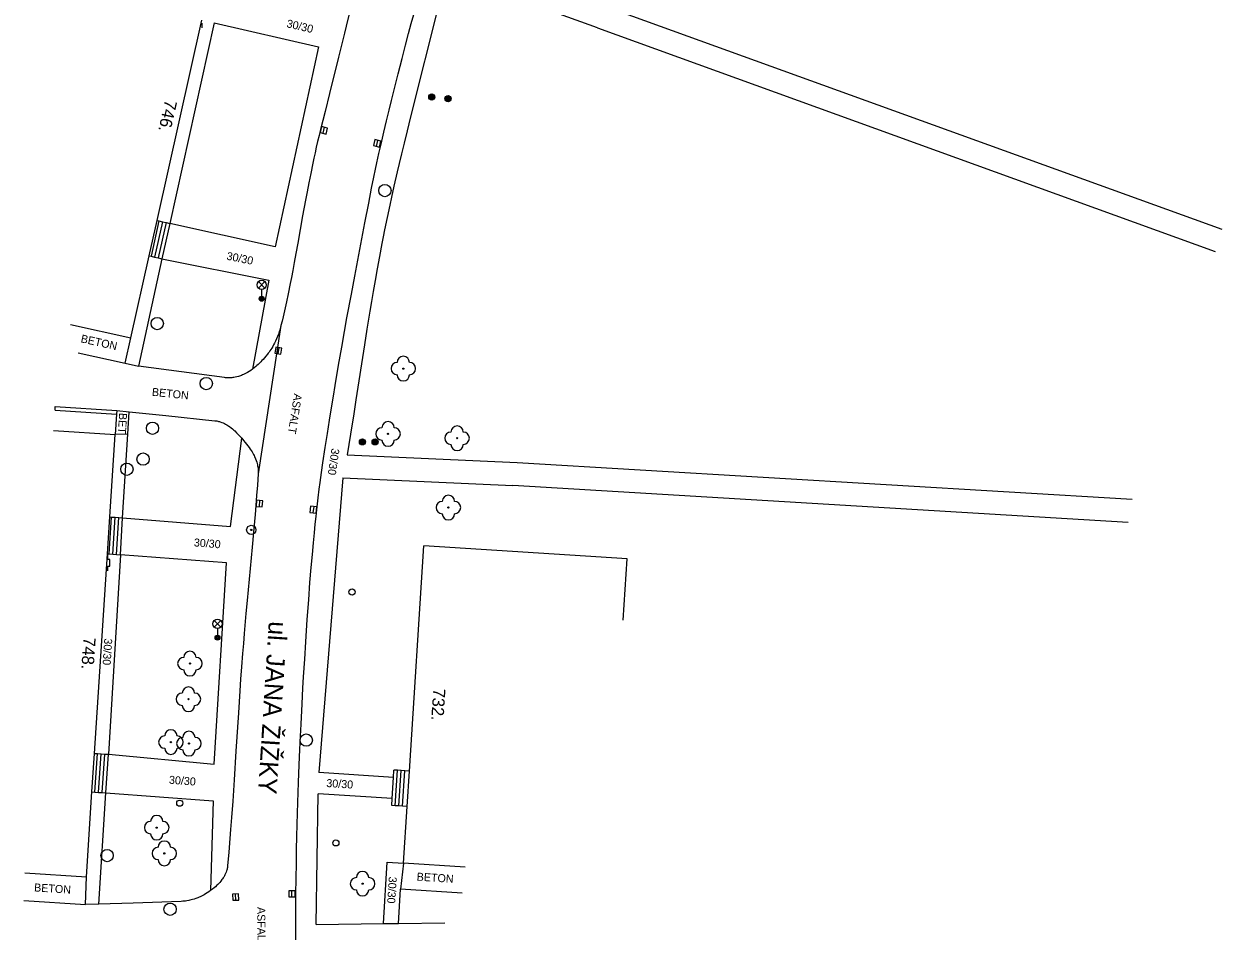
# Model space of a CAD drawing. Extents: x -539515 to -538098, y -1182060 to -1180157.
# Drawn here: x -538326.4 to -538229.1, y -1181130.7 to -1181057.1 of the extents above; entities that cross this region are included whole.
import ezdxf

# ---------------------------------------------------------------- set-up
doc = ezdxf.new("R2010")
doc.units = 0
for name, color, linetype in [('Vrstva 1', 7, 'Continuous'), ('Vrstva 13', 7, 'Continuous'), ('Vrstva 21', 7, 'Continuous'), ('Vrstva 22', 7, 'Continuous'), ('Vrstva 24', 7, 'Continuous'), ('Vrstva 25', 7, 'Continuous'), ('Vrstva 27', 7, 'Continuous'), ('Vrstva 28', 7, 'Continuous'), ('Vrstva 33', 7, 'Continuous'), ('Vrstva 40', 7, 'Continuous'), ('Vrstva 47', 7, 'Continuous'), ('Vrstva 49', 7, 'Continuous'), ('Vrstva 68', 7, 'Continuous'), ('Vrstva 88', 7, 'Continuous')]:
    doc.layers.add(name, color=color, linetype=linetype)

msp = doc.modelspace()

# ---------------------------------------------------------------- linework, layer by layer
at = {"layer": 'Vrstva 1'}
for p, q in [((-538322.649, -1181081.468), (-538317.77, -1181082.56)), ((-538324.03, -1181090.076), (-538319.04, -1181090.4)), ((-538277.453, -1181100.501), (-538293.97, -1181099.45)), ((-538277.771, -1181105.491), (-538277.453, -1181100.501)), ((-538326.36, -1181126.006), (-538321.37, -1181126.33)), ((-538290.62, -1181125.538), (-538295.61, -1181125.22))]:
    msp.add_line(p, q, dxfattribs=at)
for points in [[(-538315.634, -1181073.02), (-538311.991, -1181056.744)], [(-538316.276, -1181075.888), (-538315.634, -1181073.02)], [(-538317.77, -1181082.56), (-538316.276, -1181075.888)], [(-538319.474, -1181097.092), (-538319.04, -1181090.4)], [(-538319.668, -1181100.091), (-538319.474, -1181097.092)], [(-538295.133, -1181117.731), (-538293.97, -1181099.45)], [(-538320.719, -1181116.296), (-538319.668, -1181100.091)], [(-538320.923, -1181119.43), (-538320.719, -1181116.296)], [(-538295.317, -1181120.61), (-538295.133, -1181117.731)], [(-538321.37, -1181126.33), (-538320.923, -1181119.43)], [(-538295.61, -1181125.22), (-538295.317, -1181120.61)]]:
    msp.add_lwpolyline(points, dxfattribs=at)
at = {"layer": 'Vrstva 13'}
for p, q in [((-538279.867, -1181057.368), (-538292.13, -1181052.94)), ((-538292.748, -1181055.46), (-538295.047, -1181064.595)), ((-538229.137, -1181073.742), (-538279.247, -1181055.628)), ((-538310.98, -1181056.97), (-538314.599, -1181073.251)), ((-538310.98, -1181056.97), (-538302.53, -1181058.92)), ((-538279.867, -1181057.368), (-538229.687, -1181075.542)), ((-538302.53, -1181058.92), (-538306.03, -1181075.17)), ((-538315.477, -1181073.054), (-538316.118, -1181075.923)), ((-538315.184, -1181073.12), (-538315.825, -1181075.989)), ((-538314.891, -1181073.185), (-538315.532, -1181076.054)), ((-538314.599, -1181073.251), (-538315.24, -1181076.12)), ((-538306.03, -1181075.17), (-538314.599, -1181073.251)), ((-538315.24, -1181076.12), (-538317.15, -1181084.85)), ((-538315.24, -1181076.12), (-538306.55, -1181077.86)), ((-538306.55, -1181077.86), (-538307.89, -1181085.09)), ((-538305.57, -1181081.55), (-538307.42, -1181093.59)), ((-538318.229, -1181084.609), (-538317.77, -1181082.56)), ((-538322.029, -1181083.758), (-538318.229, -1181084.609)), ((-538318.229, -1181084.609), (-538317.15, -1181084.85)), ((-538318.929, -1181088.759), (-538319.04, -1181090.4)), ((-538318, -1181090.37), (-538319.04, -1181090.4)), ((-538309.67, -1181097.87), (-538308.75, -1181090.71)), ((-538300.2, -1181092.06), (-538286.395, -1181092.686)), ((-538286.395, -1181092.686), (-538236.432, -1181095.639)), ((-538300.55, -1181093.92), (-538302.49, -1181117.86)), ((-538300.55, -1181093.92), (-538286.745, -1181094.546)), ((-538236.752, -1181097.559), (-538286.745, -1181094.546)), ((-538319.522, -1181100.099), (-538319.328, -1181097.101)), ((-538319.222, -1181100.119), (-538319.028, -1181097.121)), ((-538318.923, -1181100.138), (-538318.729, -1181097.14)), ((-538318.6, -1181100.16), (-538318.43, -1181097.16)), ((-538318.43, -1181097.16), (-538309.67, -1181097.87)), ((-538318.6, -1181100.16), (-538319.58, -1181116.37)), ((-538309.99, -1181100.83), (-538318.6, -1181100.16)), ((-538310.99, -1181117.18), (-538309.99, -1181100.83)), ((-538320.68, -1181119.445), (-538320.478, -1181116.312)), ((-538320.38, -1181119.464), (-538320.178, -1181116.331)), ((-538320.081, -1181119.483), (-538319.879, -1181116.35)), ((-538319.782, -1181119.503), (-538319.58, -1181116.37)), ((-538319.58, -1181116.37), (-538310.99, -1181117.18)), ((-538296.438, -1181118.247), (-538302.49, -1181117.86)), ((-538296.284, -1181120.548), (-538296.1, -1181117.669)), ((-538295.985, -1181120.567), (-538295.801, -1181117.688)), ((-538295.685, -1181120.586), (-538295.501, -1181117.707)), ((-538320.368, -1181128.544), (-538319.782, -1181119.503)), ((-538319.782, -1181119.503), (-538311.08, -1181120.14)), ((-538311.08, -1181120.14), (-538311.29, -1181127.44)), ((-538302.71, -1181130.19), (-538302.55, -1181119.58)), ((-538296.548, -1181119.964), (-538302.55, -1181119.58)), ((-538297.25, -1181130.12), (-538296.933, -1181125.136)), ((-538296.933, -1181125.136), (-538295.61, -1181125.22)), ((-538295.61, -1181125.22), (-538295.85, -1181127.33)), ((-538321.45, -1181128.58), (-538321.37, -1181126.33)), ((-538296.026, -1181130.104), (-538295.85, -1181127.33)), ((-538290.86, -1181127.648), (-538295.85, -1181127.33)), ((-538326.44, -1181128.256), (-538321.45, -1181128.58))]:
    msp.add_line(p, q, dxfattribs=at)
for points in [[(-538295.047, -1181064.595), (-538295.329, -1181065.738), (-538295.572, -1181066.739), (-538295.782, -1181067.615), (-538295.963, -1181068.383), (-538296.12, -1181069.054), (-538296.389, -1181070.231), (-538296.586, -1181071.114), (-538296.731, -1181071.777), (-538296.944, -1181072.773), (-538297.15, -1181073.77), (-538297.264, -1181074.338)], [(-538315.634, -1181073.02), (-538315.477, -1181073.054), (-538315.184, -1181073.12), (-538314.891, -1181073.185), (-538314.599, -1181073.251)], [(-538297.264, -1181074.338), (-538297.373, -1181074.888), (-538297.577, -1181075.956), (-538297.761, -1181076.958), (-538297.929, -1181077.899), (-538298.082, -1181078.782), (-538298.223, -1181079.61), (-538298.352, -1181080.387), (-538298.589, -1181081.845), (-538298.791, -1181083.122)], [(-538316.276, -1181075.888), (-538316.118, -1181075.923), (-538315.825, -1181075.989), (-538315.532, -1181076.054), (-538315.24, -1181076.12)], [(-538298.791, -1181083.122), (-538299.485, -1181087.593), (-538299.66, -1181088.711), (-538299.926, -1181090.386), (-538300.062, -1181091.223), (-538300.2, -1181092.06)], [(-538318, -1181090.37), (-538317.886, -1181088.565)], [(-538318.43, -1181097.16), (-538318, -1181090.37)], [(-538319.474, -1181097.092), (-538319.328, -1181097.101), (-538319.028, -1181097.121), (-538318.729, -1181097.14), (-538318.43, -1181097.16)], [(-538319.668, -1181100.091), (-538319.522, -1181100.099), (-538319.222, -1181100.119), (-538318.923, -1181100.138), (-538318.6, -1181100.16)], [(-538320.719, -1181116.296), (-538320.478, -1181116.312), (-538320.178, -1181116.331), (-538319.879, -1181116.35), (-538319.58, -1181116.37)], [(-538296.57, -1181120.53), (-538296.548, -1181119.964), (-538296.438, -1181118.247), (-538296.4, -1181117.65)], [(-538295.133, -1181117.731), (-538295.501, -1181117.707), (-538295.801, -1181117.688), (-538296.1, -1181117.669), (-538296.4, -1181117.65)], [(-538320.923, -1181119.43), (-538320.68, -1181119.445), (-538320.38, -1181119.464), (-538320.081, -1181119.483), (-538319.782, -1181119.503)], [(-538295.317, -1181120.61), (-538295.685, -1181120.586), (-538295.985, -1181120.567), (-538296.284, -1181120.548), (-538296.57, -1181120.53)], [(-538302.71, -1181130.19), (-538297.25, -1181130.12)], [(-538297.25, -1181130.12), (-538296.026, -1181130.104), (-538292.25, -1181130.055)]]:
    msp.add_lwpolyline(points, dxfattribs=at)
at = {"layer": 'Vrstva 21'}
for radius in [0.375, 0.05]:
    msp.add_circle((-538307.98, -1181098.15), radius, dxfattribs=at)
at = {"layer": 'Vrstva 22'}
for centre in [(-538295.63, -1181085.05), (-538296.87, -1181090.35), (-538291.26, -1181090.7), (-538291.97, -1181096.33), (-538312.96, -1181109), (-538313.08, -1181111.9), (-538314.51, -1181115.38), (-538313.04, -1181115.5), (-538315.66, -1181122.33), (-538315.04, -1181124.42), (-538298.94, -1181126.88)]:
    msp.add_circle(centre, 0.05, dxfattribs=at)
for centre, start, end in [((-538295.63, -1181084.55), 0, 180), ((-538296.13, -1181085.05), 90, 270), ((-538295.13, -1181085.05), 270, 90), ((-538295.63, -1181085.55), 180, 0), ((-538297.37, -1181090.35), 90, 270), ((-538296.87, -1181089.85), 0, 180), ((-538296.37, -1181090.35), 270, 90), ((-538291.26, -1181090.2), 0, 180), ((-538296.87, -1181090.85), 180, 0), ((-538291.76, -1181090.7), 90, 270), ((-538290.76, -1181090.7), 270, 90), ((-538291.26, -1181091.2), 180, 0), ((-538292.47, -1181096.33), 90, 270), ((-538291.97, -1181095.83), 0, 180), ((-538291.47, -1181096.33), 270, 90), ((-538291.97, -1181096.83), 180, 0), ((-538313.46, -1181109), 90, 270), ((-538312.96, -1181108.5), 0, 180), ((-538312.46, -1181109), 270, 90), ((-538312.96, -1181109.5), 180, 0), ((-538313.58, -1181111.9), 90, 270), ((-538313.08, -1181111.4), 0, 180), ((-538312.58, -1181111.9), 270, 90), ((-538313.08, -1181112.4), 180, 0), ((-538314.51, -1181114.88), 0, 180), ((-538315.01, -1181115.38), 90, 270), ((-538313.54, -1181115.5), 90, 270), ((-538314.01, -1181115.38), 270, 90), ((-538313.04, -1181115), 0, 180), ((-538312.54, -1181115.5), 270, 90), ((-538314.51, -1181115.88), 180, 0), ((-538313.04, -1181116), 180, 0), ((-538316.16, -1181122.33), 90, 270), ((-538315.66, -1181121.83), 0, 180), ((-538315.16, -1181122.33), 270, 90), ((-538315.66, -1181122.83), 180, 0), ((-538315.54, -1181124.42), 90, 270), ((-538315.04, -1181123.92), 0, 180), ((-538314.54, -1181124.42), 270, 90), ((-538315.04, -1181124.92), 180, 0), ((-538298.94, -1181126.38), 0, 180), ((-538299.44, -1181126.88), 90, 270), ((-538298.44, -1181126.88), 270, 90), ((-538298.94, -1181127.38), 180, 0)]:
    msp.add_arc(centre, 0.5, start, end, dxfattribs=at)
at = {"layer": 'Vrstva 24'}
for p, q in [((-538311.96, -1181057.36), (-538311.96, -1181056.993)), ((-538319.64, -1181100.549), (-538319.64, -1181100.181)), ((-538319.457, -1181100.551), (-538319.64, -1181100.549)), ((-538319.457, -1181101.103), (-538319.457, -1181100.551)), ((-538319.64, -1181101.47), (-538319.64, -1181101.103)), ((-538319.64, -1181101.103), (-538319.457, -1181101.103))]:
    msp.add_line(p, q, dxfattribs=at)
at = {"layer": 'Vrstva 25'}
for centre, radius in [((-538293.32, -1181062.99), 0.25), ((-538293.32, -1181062.99), 0.2), ((-538293.32, -1181062.99), 0.15), ((-538293.32, -1181062.99), 0.1), ((-538293.32, -1181062.99), 0.05), ((-538292, -1181063.13), 0.25), ((-538292, -1181063.13), 0.2), ((-538292, -1181063.13), 0.15), ((-538292, -1181063.13), 0.1), ((-538292, -1181063.13), 0.05), ((-538298.95, -1181091), 0.25), ((-538298.95, -1181091), 0.2), ((-538298.95, -1181091), 0.15), ((-538298.95, -1181091), 0.1), ((-538298.95, -1181091), 0.05), ((-538297.92, -1181091), 0.25), ((-538297.92, -1181091), 0.2), ((-538297.92, -1181091), 0.15), ((-538297.92, -1181091), 0.1), ((-538297.92, -1181091), 0.05)]:
    msp.add_circle(centre, radius, dxfattribs=at)
at = {"layer": 'Vrstva 27'}
for p, q in [((-538302.139, -1181065.936), (-538302.019, -1181065.45)), ((-538297.81, -1181066.997), (-538297.7, -1181066.509)), ((-538305.73, -1181083.345), (-538305.83, -1181083.835)), ((-538307.299, -1181095.756), (-538307.339, -1181096.254)), ((-538302.911, -1181096.254), (-538302.967, -1181096.75)), ((-538309.24, -1181128.22), (-538309.26, -1181127.72)), ((-538304.676, -1181127.953), (-538304.672, -1181127.453))]:
    msp.add_line(p, q, dxfattribs=at)
for points in [[(-538301.896, -1181065.996), (-538301.776, -1181065.51), (-538302.262, -1181065.39), (-538302.382, -1181065.876)], [(-538297.566, -1181067.052), (-538297.456, -1181066.564), (-538297.944, -1181066.454), (-538298.054, -1181066.942)], [(-538305.976, -1181083.295), (-538306.075, -1181083.786), (-538305.584, -1181083.885), (-538305.485, -1181083.394)], [(-538307.548, -1181095.735), (-538307.589, -1181096.234), (-538307.09, -1181096.275), (-538307.049, -1181095.776)], [(-538303.159, -1181096.225), (-538303.216, -1181096.722), (-538302.719, -1181096.779), (-538302.662, -1181096.282)], [(-538308.99, -1181128.209), (-538309.011, -1181127.71), (-538309.51, -1181127.731), (-538309.489, -1181128.23)], [(-538304.426, -1181127.955), (-538304.422, -1181127.455), (-538304.922, -1181127.451), (-538304.926, -1181127.951)]]:
    msp.add_lwpolyline(points, close=True, dxfattribs=at)
for centre in [(-538297.13, -1181070.59), (-538315.61, -1181081.39), (-538311.63, -1181086.26), (-538316.001, -1181089.895), (-538316.77, -1181092.4), (-538318.08, -1181093.22), (-538303.51, -1181115.22), (-538319.69, -1181124.6), (-538314.57, -1181128.96)]:
    msp.add_circle(centre, 0.5, dxfattribs=at)
at = {"layer": 'Vrstva 28'}
for centre in [(-538299.795, -1181103.186), (-538313.786, -1181120.342), (-538301.11, -1181123.566)]:
    msp.add_circle(centre, 0.25, dxfattribs=at)
at = {"layer": 'Vrstva 33'}
for p, q in [((-538307.4, -1181078.514), (-538306.87, -1181077.984)), ((-538307.4, -1181077.984), (-538306.87, -1181078.514)), ((-538307.135, -1181078.624), (-538307.135, -1181079.374)), ((-538310.985, -1181106.04), (-538310.455, -1181105.51)), ((-538310.985, -1181105.51), (-538310.455, -1181106.04)), ((-538310.72, -1181106.15), (-538310.72, -1181106.9))]:
    msp.add_line(p, q, dxfattribs=at)
for centre, radius in [((-538307.135, -1181078.249), 0.375), ((-538307.135, -1181079.374), 0.2), ((-538307.135, -1181079.374), 0.145), ((-538307.135, -1181079.374), 0.0876), ((-538310.72, -1181105.775), 0.375), ((-538310.72, -1181106.9), 0.2), ((-538310.72, -1181106.9), 0.145), ((-538310.72, -1181106.9), 0.0876)]:
    msp.add_circle(centre, radius, dxfattribs=at)
at = {"layer": 'Vrstva 68'}
msp.add_line((-538323.919, -1181088.435), (-538318.929, -1181088.759), dxfattribs=at)
for points in [[(-538323.919, -1181088.435), (-538323.9, -1181088.136)], [(-538323.9, -1181088.136), (-538318.91, -1181088.46)], [(-538318.91, -1181088.46), (-538318.929, -1181088.759)]]:
    msp.add_lwpolyline(points, dxfattribs=at)
at = {"layer": 'Vrstva 88'}
for points in [[(-538298.019, -1181049.062), (-538298.114, -1181049.372), (-538298.19, -1181049.62), (-538298.34, -1181050.115), (-538298.483, -1181050.595), (-538298.754, -1181051.526), (-538299.001, -1181052.402), (-538299.228, -1181053.224), (-538299.436, -1181053.995), (-538299.629, -1181054.72), (-538299.806, -1181055.4), (-538300.133, -1181056.677), (-538300.414, -1181057.795)], [(-538296.787, -1181064.071), (-538296.591, -1181063.265), (-538296.405, -1181062.51), (-538296.052, -1181061.096), (-538295.736, -1181059.86), (-538295.455, -1181058.78), (-538295.205, -1181057.837), (-538294.983, -1181057.012), (-538294.787, -1181056.291), (-538294.439, -1181055.03)], [(-538300.414, -1181057.795), (-538300.899, -1181059.754), (-538301.619, -1181062.694), (-538301.982, -1181064.163), (-538302.35, -1181065.63), (-538302.473, -1181066.122), (-538302.588, -1181066.6), (-538302.696, -1181067.063)], [(-538297.211, -1181065.85), (-538296.993, -1181064.931), (-538296.787, -1181064.071)], [(-538299.168, -1181075.376), (-538298.75, -1181073.2), (-538298.441, -1181071.603), (-538298.205, -1181070.407), (-538298.023, -1181069.511), (-538297.883, -1181068.84), (-538297.776, -1181068.337), (-538297.611, -1181067.583), (-538297.44, -1181066.83), (-538297.211, -1181065.85)], [(-538302.696, -1181067.063), (-538302.797, -1181067.512), (-538302.893, -1181067.948), (-538302.984, -1181068.371), (-538303.154, -1181069.191)], [(-538303.154, -1181069.191), (-538303.307, -1181069.961), (-538303.446, -1181070.684), (-538303.573, -1181071.362), (-538303.806, -1181072.636), (-538304.207, -1181074.868), (-538304.359, -1181075.705), (-538304.494, -1181076.438), (-538304.615, -1181077.078), (-538304.723, -1181077.639), (-538304.819, -1181078.129), (-538304.993, -1181078.986)], [(-538299.58, -1181077.552), (-538299.168, -1181075.376)], [(-538301.167, -1181086.411), (-538300.884, -1181084.756), (-538300.631, -1181083.309), (-538300.406, -1181082.044), (-538300.206, -1181080.938), (-538299.851, -1181079.002), (-538299.58, -1181077.552)], [(-538304.993, -1181078.986), (-538305.129, -1181079.628)], [(-538305.129, -1181079.628), (-538305.235, -1181080.109), (-538305.398, -1181080.83), (-538305.483, -1181081.19), (-538305.57, -1181081.55), (-538305.603, -1181081.679), (-538305.636, -1181081.802), (-538305.671, -1181081.921), (-538305.706, -1181082.035), (-538305.779, -1181082.252), (-538305.855, -1181082.453), (-538305.931, -1181082.639), (-538306.009, -1181082.81), (-538306.086, -1181082.969), (-538306.163, -1181083.115), (-538306.238, -1181083.251), (-538306.313, -1181083.377), (-538306.386, -1181083.493), (-538306.458, -1181083.601), (-538306.527, -1181083.702), (-538306.595, -1181083.795), (-538306.66, -1181083.881), (-538306.788, -1181084.042), (-538306.905, -1181084.18), (-538307.013, -1181084.299), (-538307.11, -1181084.402), (-538307.198, -1181084.491), (-538307.277, -1181084.568), (-538307.421, -1181084.702), (-538307.533, -1181084.801), (-538307.619, -1181084.874), (-538307.752, -1181084.983), (-538307.89, -1181085.09), (-538308.026, -1181085.19), (-538308.154, -1181085.276), (-538308.275, -1181085.352), (-538308.389, -1181085.417), (-538308.496, -1181085.474), (-538308.597, -1181085.524), (-538308.692, -1181085.566), (-538308.781, -1181085.603), (-538308.865, -1181085.635), (-538308.944, -1181085.662), (-538309.018, -1181085.686), (-538309.157, -1181085.724), (-538309.279, -1181085.752), (-538309.387, -1181085.771), (-538309.481, -1181085.784), (-538309.564, -1181085.793), (-538309.637, -1181085.798), (-538309.764, -1181085.803), (-538309.86, -1181085.803), (-538310.005, -1181085.795), (-538310.077, -1181085.789), (-538310.15, -1181085.78)], [(-538310.15, -1181085.78), (-538313.65, -1181085.315), (-538317.15, -1181084.85)], [(-538302.542, -1181095.553), (-538302.454, -1181094.837), (-538302.384, -1181094.3), (-538302.275, -1181093.495), (-538302.16, -1181092.69), (-538301.977, -1181091.465), (-538301.8, -1181090.318), (-538301.631, -1181089.243), (-538301.469, -1181088.237), (-538301.314, -1181087.294), (-538301.167, -1181086.411)], [(-538318.91, -1181088.46), (-538317.886, -1181088.565), (-538314.92, -1181088.87), (-538310.93, -1181089.28), (-538310.85, -1181089.29), (-538310.773, -1181089.302), (-538310.699, -1181089.317), (-538310.629, -1181089.333), (-538310.561, -1181089.351), (-538310.496, -1181089.371), (-538310.373, -1181089.414), (-538310.26, -1181089.461), (-538310.156, -1181089.51), (-538310.059, -1181089.56), (-538309.97, -1181089.611), (-538309.888, -1181089.662), (-538309.812, -1181089.713), (-538309.741, -1181089.762), (-538309.611, -1181089.861), (-538309.499, -1181089.952), (-538309.402, -1181090.037), (-538309.318, -1181090.113)], [(-538309.318, -1181090.113), (-538309.173, -1181090.253), (-538309.066, -1181090.362), (-538308.907, -1181090.533), (-538308.75, -1181090.71), (-538308.606, -1181090.879), (-538308.475, -1181091.038), (-538308.356, -1181091.187), (-538308.249, -1181091.329), (-538308.152, -1181091.462), (-538308.066, -1181091.587), (-538307.988, -1181091.706), (-538307.919, -1181091.817), (-538307.858, -1181091.923), (-538307.803, -1181092.022), (-538307.754, -1181092.115), (-538307.711, -1181092.203), (-538307.673, -1181092.287), (-538307.639, -1181092.365), (-538307.582, -1181092.513), (-538307.538, -1181092.643), (-538307.504, -1181092.758), (-538307.479, -1181092.859), (-538307.461, -1181092.949), (-538307.447, -1181093.027), (-538307.428, -1181093.166), (-538307.419, -1181093.271), (-538307.416, -1181093.35), (-538307.415, -1181093.469), (-538307.42, -1181093.59), (-538307.484, -1181094.502), (-538307.549, -1181095.357), (-538307.613, -1181096.159), (-538307.675, -1181096.91), (-538307.798, -1181098.319)], [(-538302.781, -1181097.68), (-538302.715, -1181097.055), (-538302.654, -1181096.509), (-538302.542, -1181095.553)], [(-538303.55, -1181107.25), (-538303.428, -1181105.424), (-538303.315, -1181103.828), (-538303.21, -1181102.432), (-538303.111, -1181101.211), (-538303.019, -1181100.144), (-538302.933, -1181099.21), (-538302.854, -1181098.394), (-538302.781, -1181097.68)], [(-538307.798, -1181098.319), (-538307.91, -1181099.552)], [(-538307.91, -1181099.552), (-538308.313, -1181103.869), (-538308.411, -1181104.948), (-538308.554, -1181106.567), (-538308.622, -1181107.376), (-538308.687, -1181108.186), (-538308.769, -1181109.263)], [(-538304.085, -1181117.225), (-538304.032, -1181115.978), (-538303.982, -1181114.887), (-538303.936, -1181113.932), (-538303.85, -1181112.262), (-538303.78, -1181111.009), (-538303.726, -1181110.069), (-538303.64, -1181108.659), (-538303.55, -1181107.25)], [(-538308.769, -1181109.263), (-538308.842, -1181110.273), (-538308.908, -1181111.22), (-538309.025, -1181112.996)], [(-538309.025, -1181112.996), (-538309.221, -1181116.105), (-538309.369, -1181118.436), (-538309.486, -1181120.185), (-538309.579, -1181121.497), (-538309.653, -1181122.48)], [(-538304.141, -1181118.65), (-538304.085, -1181117.225)], [(-538304.35, -1181127.72), (-538304.337, -1181126.44), (-538304.319, -1181125.241), (-538304.298, -1181124.116), (-538304.275, -1181123.062), (-538304.25, -1181122.074), (-538304.224, -1181121.147), (-538304.197, -1181120.279), (-538304.141, -1181118.65)], [(-538309.653, -1181122.48), (-538309.711, -1181123.218), (-538309.802, -1181124.324), (-538309.9, -1181125.43), (-538309.908, -1181125.506), (-538309.919, -1181125.578), (-538309.933, -1181125.648), (-538309.948, -1181125.714), (-538309.965, -1181125.778), (-538309.983, -1181125.84), (-538310.024, -1181125.956)], [(-538310.024, -1181125.956), (-538310.068, -1181126.064), (-538310.115, -1181126.163), (-538310.164, -1181126.254), (-538310.213, -1181126.338), (-538310.262, -1181126.416), (-538310.311, -1181126.488), (-538310.359, -1181126.554), (-538310.455, -1181126.676), (-538310.544, -1181126.78), (-538310.626, -1181126.869), (-538310.701, -1181126.945), (-538310.769, -1181127.011), (-538310.892, -1181127.123), (-538310.988, -1181127.205), (-538311.136, -1181127.325), (-538311.29, -1181127.44), (-538311.433, -1181127.54), (-538311.567, -1181127.629), (-538311.693, -1181127.708), (-538311.811, -1181127.777), (-538311.923, -1181127.839)], [(-538311.923, -1181127.839), (-538312.028, -1181127.893), (-538312.127, -1181127.941), (-538312.22, -1181127.983), (-538312.307, -1181128.021), (-538312.473, -1181128.085), (-538312.618, -1181128.136), (-538312.746, -1181128.175), (-538312.859, -1181128.205), (-538312.958, -1181128.229), (-538313.046, -1181128.248), (-538313.2, -1181128.275), (-538313.316, -1181128.292), (-538313.404, -1181128.302), (-538313.536, -1181128.313), (-538313.67, -1181128.32), (-538317.56, -1181128.45), (-538320.368, -1181128.544), (-538321.45, -1181128.58)], [(-538304.152, -1181137.693), (-538304.183, -1181137.07), (-538304.209, -1181136.485), (-538304.252, -1181135.39), (-538304.284, -1181134.431), (-538304.306, -1181133.592), (-538304.323, -1181132.858), (-538304.334, -1181132.216), (-538304.349, -1181131.092), (-538304.355, -1181130.249), (-538304.357, -1181129.616), (-538304.356, -1181128.668), (-538304.35, -1181127.72)]]:
    msp.add_lwpolyline(points, dxfattribs=at)

# ---------------------------------------------------------------- texts
at = {"layer": 'Vrstva 40'}
for s, rotation, p in [('30/30', 347.00191, (-538305.154, -1181057.313)), ('30/30', 348.67739, (-538310.026, -1181076.196)), ('BETON', 347.38418, (-538321.87, -1181082.904)), ('BETON', 354.13305, (-538316.073, -1181087.25)), ('ASFALT', 261.1349, (-538304.498, -1181087.048)), ('BET', 266.37843, (-538318.706, -1181088.631)), ('30/30', 261.81813, (-538301.456, -1181091.495)), ('30/30', 355.54954, (-538312.661, -1181099.481)), ('30/30', 266.28966, (-538319.912, -1181106.943)), ('30/30', 355.81333, (-538314.68, -1181118.759)), ('30/30', 356.33928, (-538301.899, -1181119.024)), ('BETON', 356.35362, (-538294.559, -1181126.627)), ('BETON', 356.28501, (-538325.632, -1181127.503)), ('30/30', 266.36069, (-538296.807, -1181126.297)), ('ASFALT', 270.52453, (-538307.494, -1181128.775))]:
    msp.add_text(s, height=0.65, rotation=rotation, dxfattribs=at).set_placement(p)
at = {"layer": 'Vrstva 47'}
for s, rotation, p in [('746.', 257.38183, (-538314.967, -1181063.17)), ('748.', 266.28966, (-538321.61, -1181106.846)), ('732.', 266.35861, (-538293.202, -1181111.008))]:
    msp.add_text(s, height=1, rotation=rotation, dxfattribs=at).set_placement(p)
at = {"layer": 'Vrstva 49'}
msp.add_text('ul. JANA ŽIŽKY', height=1.5, rotation=266.39146, dxfattribs=at).set_placement((-538306.55, -1181105.539))

doc.saveas('drawing.dxf')
